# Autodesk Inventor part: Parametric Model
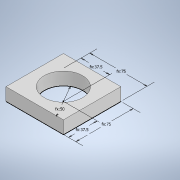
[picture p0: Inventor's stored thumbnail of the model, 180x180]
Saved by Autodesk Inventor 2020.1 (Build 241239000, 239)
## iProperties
Created: 2019-09
Part Number: Parametric Model
Material: Generic
Document SubType Name: Modeling
Designer: Synergysoft Dell02
Density: 1 g/cm^3
Appearance: Default
Author: Synergysoft Dell02
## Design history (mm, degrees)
sketch "Sketch1"
  geometry: L1 (0, 0)-(-75, 0); L2 (-75, 0)-(-75, -75); L3 (-75, -75)-(0, -75); L4 (0, -75)-(0, 0); C1 r 25 at (-37.5, -37.5)
  constraints: 8 end point, 2 parallel, 1 centre point, 1 horizontal, 1 horizontal alignment, 1 perpendicular, 1 vertical alignment, 1 other
  dimensions: "d3" = 37.5 distance from line of C1.centre L4 (derived); "d4" = 37.5 distance from line of L1 C1.centre (derived)
extrude "Extrusion1" new body sketch "Sketch1" taper "d6" = 0 deg
body "Solid1"
